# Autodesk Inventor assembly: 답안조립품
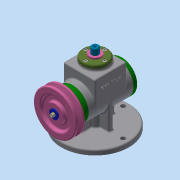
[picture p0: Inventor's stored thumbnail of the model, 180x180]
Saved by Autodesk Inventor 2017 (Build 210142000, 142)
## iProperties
Part Number: 답안조립품
Material: 일반
Document SubType Name: Assembly
Designer: 7-1
Mass: 2032.86 g
Surface Area: 1710.75 cm^2
Volume: 597.928 cm^3
Density: 3.39984 g/cm^3
Author: 7-1
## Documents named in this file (18)
- C:\Users\7-1\Desktop\600906V1037\답안조립품.iam
- C:\Users\7-1\Desktop\600906V1037\본체.ipt
- C:\Users\7-1\Desktop\600906V1037\V-벨트풀리.ipt
- C:\Users\7-1\Desktop\600906V1037\가변스프링.ipt
- C:\Users\7-1\Desktop\600906V1037\가이드부시.ipt
- C:\Users\7-1\Desktop\600906V1037\뒤커버.ipt
- C:\Users\7-1\Desktop\600906V1037\멈춤링.ipt
- C:\Users\7-1\Desktop\600906V1037\베어링 6203.ipt
- C:\Users\7-1\Desktop\600906V1037\볼트 M4.ipt
- C:\Users\7-1\Desktop\600906V1037\상부커버.ipt
- C:\Users\7-1\Desktop\600906V1037\스프링와셔.ipt
- C:\Users\7-1\Desktop\600906V1037\스프링조립용 와셔.ipt
- C:\Users\7-1\Desktop\600906V1037\슬라이더.ipt
- C:\Users\7-1\Desktop\600906V1037\앞커버.ipt
- C:\Users\7-1\Desktop\600906V1037\오일 실 17 30 5.ipt
- C:\Users\7-1\Desktop\600906V1037\키 4x4x12.ipt
- C:\Users\7-1\Desktop\600906V1037\편심축.ipt
- C:\Users\7-1\Desktop\600906V1037\평와셔.ipt
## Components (3 placed, 3 different names)
1. V-벨트풀리:1
2. 가변스프링:1
3. 가이드부시:1
